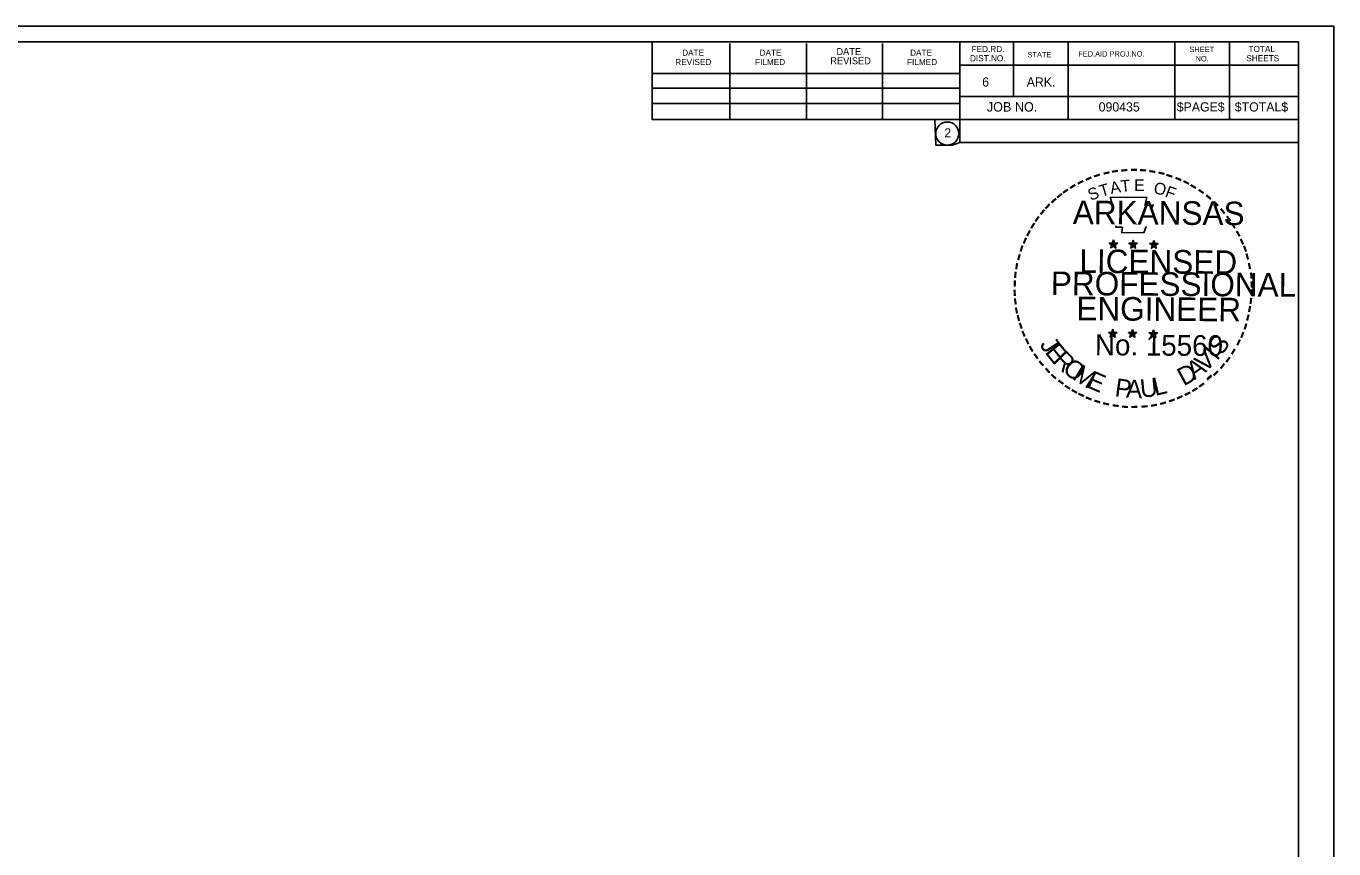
# Model space of a CAD drawing. Extents: x -1.3 to 32.1, y -0.2 to 20.7.
# Drawn here: x 15.42 to 32.07, y 10.27 to 20.75 of the extents above; entities that cross this region are included whole.
import ezdxf

# ---------------------------------------------------------------- set-up
doc = ezdxf.new("R2010")
doc.units = 0
for name, color, linetype in [('Level 1', 7, 'Continuous'), ('Level 49', 7, 'Continuous'), ('Level 62', 7, 'Continuous'), ('Level 63', 7, 'Continuous')]:
    doc.layers.add(name, color=color, linetype=linetype)

msp = doc.modelspace()

# ---------------------------------------------------------------- linework, layer by layer
at = {"layer": 'Level 1'}
for p, q in [((-0.001, 20.545), (31.617, 20.545)), ((23.391, 19.557), (23.391, 20.545)), ((24.377, 19.557), (24.377, 20.525)), ((25.353, 19.557), (25.353, 20.525)), ((26.321, 19.557), (26.321, 20.525)), ((27.307, 20.545), (27.307, 19.265)), ((27.991, 20.545), (27.991, 19.851)), ((28.685, 20.545), (28.685, 19.557)), ((30.043, 20.545), (30.043, 19.557)), ((30.737, 20.545), (30.737, 19.557)), ((31.617, -0.001), (31.617, 20.545)), ((23.391, 20.143), (27.307, 20.143)), ((31.617, 20.251), (27.307, 20.251)), ((31.617, 20.253), (31.617, 20.253)), ((23.391, 19.957), (27.307, 19.957)), ((31.617, 19.851), (27.307, 19.851)), ((23.391, 19.557), (23.391, 19.763)), ((23.391, 19.763), (27.307, 19.763)), ((31.617, 19.557), (23.391, 19.557)), ((27.307, 19.557), (27.307, 19.274)), ((27.307, 19.265), (31.617, 19.265))]:
    msp.add_line(p, q, dxfattribs=at)
msp.add_lwpolyline([(-0.001, 20.545), (23.391, 20.545), (23.391, 19.557), (27.307, 19.557), (27.307, 19.265), (31.617, 19.265), (31.617, 8.293), (-0.001, 8.293)], close=True, dxfattribs=at)
msp.add_circle((27.146, 19.379), 0.147, dxfattribs=at)
at = {"layer": 'Level 49'}
for p, q in [((29.208, 17.984), (29.262, 17.968)), ((29.208, 17.984), (29.247, 17.982)), ((29.208, 17.984), (29.247, 17.981)), ((29.208, 17.984), (29.243, 17.975)), ((29.208, 17.984), (29.243, 17.969)), ((29.208, 17.984), (29.243, 17.968)), ((29.208, 17.984), (29.243, 17.962)), ((29.262, 18.025), (29.255, 17.984)), ((29.262, 18.025), (29.255, 17.988)), ((29.262, 18.025), (29.258, 17.988)), ((29.262, 17.968), (29.262, 18.025)), ((29.262, 18.025), (29.271, 17.984)), ((29.262, 18.025), (29.269, 17.988)), ((29.262, 18.025), (29.264, 17.988)), ((29.314, 17.984), (29.262, 17.968)), ((29.314, 17.984), (29.266, 17.981)), ((29.314, 17.984), (29.271, 17.977)), ((29.314, 17.984), (29.271, 17.973)), ((29.314, 17.984), (29.279, 17.973)), ((29.314, 17.984), (29.284, 17.969)), ((29.314, 17.984), (29.286, 17.968)), ((29.458, 17.982), (29.512, 17.968)), ((29.458, 17.982), (29.497, 17.981)), ((29.458, 17.982), (29.497, 17.977)), ((29.458, 17.982), (29.497, 17.975)), ((29.458, 17.982), (29.495, 17.968)), ((29.458, 17.982), (29.495, 17.966)), ((29.458, 17.982), (29.495, 17.96)), ((29.512, 18.021), (29.505, 17.982)), ((29.512, 18.021), (29.505, 17.984)), ((29.512, 18.021), (29.506, 17.984)), ((29.512, 17.968), (29.512, 18.021)), ((29.512, 18.021), (29.521, 17.982)), ((29.512, 18.021), (29.519, 17.984)), ((29.512, 18.021), (29.514, 17.984)), ((29.564, 17.982), (29.512, 17.968)), ((29.564, 17.982), (29.518, 17.981)), ((29.564, 17.982), (29.521, 17.975)), ((29.564, 17.982), (29.521, 17.973)), ((29.564, 17.982), (29.529, 17.969)), ((29.564, 17.982), (29.534, 17.968)), ((29.564, 17.982), (29.536, 17.966)), ((29.723, 17.981), (29.777, 17.962)), ((29.723, 17.981), (29.766, 17.975)), ((29.723, 17.981), (29.762, 17.973)), ((29.723, 17.981), (29.762, 17.969)), ((29.723, 17.981), (29.76, 17.966)), ((29.723, 17.981), (29.76, 17.96)), ((29.723, 17.981), (29.76, 17.96)), ((29.777, 18.018), (29.768, 17.982)), ((29.777, 18.018), (29.773, 17.981)), ((29.777, 18.018), (29.773, 17.981)), ((29.777, 17.962), (29.777, 18.018)), ((29.777, 18.018), (29.788, 17.981)), ((29.777, 18.018), (29.784, 17.981)), ((29.777, 18.018), (29.781, 17.981)), ((29.829, 17.981), (29.777, 17.962)), ((29.829, 17.981), (29.782, 17.975)), ((29.829, 17.981), (29.788, 17.973)), ((29.829, 17.981), (29.788, 17.968)), ((29.829, 17.981), (29.795, 17.966)), ((29.829, 17.981), (29.797, 17.966)), ((29.829, 17.981), (29.803, 17.962)), ((29.23, 17.923), (29.262, 17.968)), ((29.23, 17.923), (29.243, 17.966)), ((29.23, 17.923), (29.247, 17.96)), ((29.23, 17.923), (29.249, 17.958)), ((29.23, 17.923), (29.255, 17.955)), ((29.23, 17.923), (29.262, 17.955)), ((29.23, 17.923), (29.262, 17.951)), ((29.293, 17.921), (29.262, 17.968)), ((29.293, 17.921), (29.262, 17.955)), ((29.293, 17.921), (29.262, 17.951)), ((29.293, 17.921), (29.266, 17.955)), ((29.293, 17.921), (29.271, 17.966)), ((29.293, 17.921), (29.271, 17.96)), ((29.293, 17.921), (29.277, 17.968)), ((29.481, 17.921), (29.512, 17.968)), ((29.481, 17.921), (29.497, 17.962)), ((29.481, 17.921), (29.497, 17.96)), ((29.481, 17.921), (29.499, 17.958)), ((29.481, 17.921), (29.505, 17.953)), ((29.481, 17.921), (29.512, 17.953)), ((29.481, 17.921), (29.512, 17.951)), ((29.544, 17.921), (29.512, 17.968)), ((29.544, 17.921), (29.512, 17.953)), ((29.544, 17.921), (29.512, 17.951)), ((29.544, 17.921), (29.518, 17.953)), ((29.544, 17.921), (29.521, 17.966)), ((29.544, 17.921), (29.521, 17.958)), ((29.544, 17.921), (29.527, 17.966)), ((29.744, 17.919), (29.777, 17.962)), ((29.744, 17.919), (29.762, 17.96)), ((29.744, 17.919), (29.766, 17.955)), ((29.744, 17.919), (29.766, 17.953)), ((29.744, 17.919), (29.777, 17.953)), ((29.744, 17.919), (29.773, 17.951)), ((29.744, 17.919), (29.781, 17.945)), ((29.807, 17.919), (29.777, 17.962)), ((29.807, 17.919), (29.777, 17.953)), ((29.807, 17.919), (29.777, 17.945)), ((29.807, 17.919), (29.782, 17.951)), ((29.807, 17.919), (29.788, 17.96)), ((29.807, 17.919), (29.788, 17.955)), ((29.807, 17.919), (29.792, 17.96)), ((29.201, 16.847), (29.255, 16.83)), ((29.201, 16.847), (29.24, 16.845)), ((29.201, 16.847), (29.238, 16.839)), ((29.201, 16.847), (29.238, 16.839)), ((29.201, 16.847), (29.238, 16.832)), ((29.201, 16.847), (29.238, 16.83)), ((29.201, 16.847), (29.238, 16.828)), ((29.219, 16.789), (29.255, 16.83)), ((29.219, 16.789), (29.238, 16.83)), ((29.219, 16.789), (29.24, 16.823)), ((29.219, 16.789), (29.242, 16.823)), ((29.219, 16.789), (29.255, 16.821)), ((29.219, 16.789), (29.247, 16.817)), ((29.219, 16.789), (29.255, 16.815)), ((29.255, 16.888), (29.243, 16.851)), ((29.255, 16.888), (29.247, 16.847)), ((29.255, 16.888), (29.249, 16.847)), ((29.284, 16.786), (29.251, 16.815)), ((29.255, 16.83), (29.255, 16.888)), ((29.255, 16.888), (29.262, 16.847)), ((29.255, 16.888), (29.262, 16.847)), ((29.255, 16.888), (29.255, 16.847)), ((29.306, 16.847), (29.255, 16.83)), ((29.284, 16.786), (29.255, 16.83)), ((29.284, 16.786), (29.255, 16.817)), ((29.284, 16.786), (29.256, 16.817)), ((29.306, 16.847), (29.258, 16.845)), ((29.306, 16.847), (29.262, 16.839)), ((29.306, 16.847), (29.262, 16.838)), ((29.284, 16.786), (29.262, 16.83)), ((29.284, 16.786), (29.262, 16.823)), ((29.306, 16.847), (29.269, 16.836)), ((29.284, 16.786), (29.269, 16.83)), ((29.306, 16.847), (29.273, 16.832)), ((29.306, 16.847), (29.277, 16.83)), ((29.451, 16.847), (29.505, 16.83)), ((29.451, 16.847), (29.49, 16.843)), ((29.451, 16.847), (29.49, 16.839)), ((29.451, 16.847), (29.49, 16.838)), ((29.451, 16.847), (29.488, 16.832)), ((29.451, 16.847), (29.488, 16.828)), ((29.451, 16.847), (29.488, 16.825)), ((29.469, 16.786), (29.505, 16.83)), ((29.469, 16.786), (29.49, 16.828)), ((29.469, 16.786), (29.49, 16.821)), ((29.469, 16.786), (29.492, 16.821)), ((29.469, 16.786), (29.497, 16.817)), ((29.469, 16.786), (29.505, 16.817)), ((29.469, 16.786), (29.505, 16.813)), ((29.505, 16.884), (29.495, 16.847)), ((29.505, 16.884), (29.497, 16.847)), ((29.505, 16.884), (29.499, 16.847)), ((29.534, 16.786), (29.503, 16.813)), ((29.505, 16.83), (29.505, 16.884)), ((29.505, 16.884), (29.512, 16.845)), ((29.505, 16.884), (29.512, 16.845)), ((29.505, 16.884), (29.505, 16.847)), ((29.555, 16.845), (29.505, 16.83)), ((29.534, 16.786), (29.505, 16.83)), ((29.534, 16.786), (29.505, 16.817)), ((29.534, 16.786), (29.506, 16.817)), ((29.555, 16.845), (29.51, 16.845)), ((29.555, 16.845), (29.512, 16.838)), ((29.555, 16.845), (29.512, 16.838)), ((29.534, 16.786), (29.512, 16.828)), ((29.534, 16.786), (29.512, 16.823)), ((29.555, 16.845), (29.519, 16.832)), ((29.534, 16.786), (29.519, 16.828)), ((29.555, 16.845), (29.525, 16.83)), ((29.555, 16.845), (29.527, 16.828)), ((29.716, 16.843), (29.77, 16.825)), ((29.716, 16.843), (29.755, 16.839)), ((29.716, 16.843), (29.755, 16.836)), ((29.716, 16.843), (29.753, 16.832)), ((29.716, 16.843), (29.753, 16.828)), ((29.716, 16.843), (29.751, 16.825)), ((29.716, 16.843), (29.751, 16.821)), ((29.736, 16.782), (29.77, 16.825)), ((29.736, 16.782), (29.753, 16.825)), ((29.736, 16.782), (29.755, 16.817)), ((29.736, 16.782), (29.758, 16.817)), ((29.736, 16.782), (29.762, 16.813)), ((29.736, 16.782), (29.768, 16.813)), ((29.77, 16.882), (29.76, 16.843)), ((29.77, 16.882), (29.762, 16.843)), ((29.77, 16.882), (29.766, 16.843)), ((29.799, 16.782), (29.768, 16.813)), ((29.77, 16.825), (29.77, 16.882)), ((29.77, 16.882), (29.777, 16.843)), ((29.77, 16.882), (29.777, 16.843)), ((29.77, 16.882), (29.77, 16.843)), ((29.821, 16.843), (29.77, 16.825)), ((29.799, 16.782), (29.77, 16.825)), ((29.799, 16.782), (29.773, 16.813)), ((29.821, 16.843), (29.775, 16.839)), ((29.821, 16.843), (29.777, 16.836)), ((29.821, 16.843), (29.777, 16.832)), ((29.799, 16.782), (29.777, 16.817)), ((29.799, 16.782), (29.781, 16.825)), ((29.799, 16.782), (29.782, 16.825)), ((29.821, 16.843), (29.788, 16.83)), ((29.821, 16.843), (29.79, 16.825)), ((29.821, 16.843), (29.792, 16.825)), ((29.736, 16.782), (29.77, 16.81)), ((29.799, 16.782), (29.768, 16.81))]:
    msp.add_line(p, q, dxfattribs=at)
for points in [[(29.219, 18.568), (29.256, 18.442)], [(29.745, 18.425), (29.768, 18.47), (29.662, 18.464), (29.686, 18.564), (29.219, 18.568)], [(29.292, 18.203), (29.292, 18.188), (29.375, 18.186), (29.368, 18.118), (29.647, 18.116), (29.677, 18.194)], [(29.262, 18.025), (29.293, 17.921), (29.208, 17.984), (29.314, 17.984), (29.23, 17.923), (29.262, 18.025)], [(29.512, 18.021), (29.544, 17.921), (29.458, 17.982), (29.564, 17.982), (29.481, 17.921), (29.512, 18.021)], [(29.777, 18.018), (29.807, 17.919), (29.723, 17.981), (29.829, 17.981), (29.744, 17.919), (29.777, 18.018)], [(29.255, 16.888), (29.284, 16.786), (29.201, 16.847), (29.306, 16.847), (29.219, 16.789), (29.255, 16.888)], [(29.505, 16.884), (29.534, 16.786), (29.451, 16.847), (29.555, 16.845), (29.469, 16.786), (29.505, 16.884)], [(29.77, 16.882), (29.799, 16.782), (29.716, 16.843), (29.821, 16.843), (29.736, 16.782), (29.77, 16.882)], [(30.464, 16.241), (30.457, 16.265), (30.501, 16.302)], [(30.498, 16.308), (30.505, 16.286), (30.46, 16.247)], [(30.505, 16.289), (30.46, 16.25)], [(30.505, 16.286), (30.462, 16.248)]]:
    msp.add_lwpolyline(points, dxfattribs=at)
for centre, radius in [((29.263, 17.967), 0.0259), ((29.263, 17.967), 0.0234), ((29.263, 17.967), 0.0217), ((29.263, 17.967), 0.0199), ((29.263, 17.967), 0.0174), ((29.263, 17.967), 0.0161), ((29.263, 17.967), 0.0149), ((29.263, 17.967), 0.0128), ((29.513, 17.965), 0.0259), ((29.513, 17.965), 0.0234), ((29.513, 17.965), 0.0217), ((29.513, 17.965), 0.0199), ((29.513, 17.965), 0.0174), ((29.513, 17.965), 0.0161), ((29.513, 17.965), 0.0149), ((29.779, 17.961), 0.0259), ((29.779, 17.961), 0.0234), ((29.779, 17.961), 0.0217), ((29.779, 17.961), 0.0199), ((29.263, 17.967), 0.0112), ((29.263, 17.967), 0.00933), ((29.263, 17.967), 0.00744), ((29.263, 17.967), 0.00555), ((29.263, 17.967), 0.00445), ((29.263, 17.967), 0.00216), ((29.513, 17.965), 0.0128), ((29.513, 17.965), 0.0112), ((29.513, 17.965), 0.00933), ((29.513, 17.965), 0.00744), ((29.513, 17.965), 0.00555), ((29.513, 17.965), 0.00445), ((29.513, 17.965), 0.00216), ((29.779, 17.961), 0.0174), ((29.779, 17.961), 0.0161), ((29.779, 17.961), 0.0149), ((29.779, 17.961), 0.0128), ((29.779, 17.961), 0.0112), ((29.779, 17.961), 0.00933), ((29.779, 17.961), 0.00744), ((29.779, 17.961), 0.00555), ((29.779, 17.961), 0.00445), ((29.779, 17.961), 0.00216), ((29.254, 16.83), 0.0259), ((29.254, 16.83), 0.0234), ((29.254, 16.83), 0.0217), ((29.254, 16.83), 0.0199), ((29.254, 16.83), 0.0174), ((29.254, 16.83), 0.0161), ((29.254, 16.83), 0.0149), ((29.254, 16.83), 0.0128), ((29.254, 16.83), 0.0112), ((29.254, 16.83), 0.00933), ((29.254, 16.83), 0.00744), ((29.254, 16.83), 0.00555), ((29.254, 16.83), 0.00445), ((29.254, 16.83), 0.00216), ((29.505, 16.828), 0.0259), ((29.505, 16.828), 0.0234), ((29.505, 16.828), 0.0217), ((29.505, 16.828), 0.0199), ((29.505, 16.828), 0.0174), ((29.505, 16.828), 0.0161), ((29.505, 16.828), 0.0149), ((29.505, 16.828), 0.0128), ((29.505, 16.828), 0.0112), ((29.505, 16.828), 0.00933), ((29.505, 16.828), 0.00744), ((29.505, 16.828), 0.00555), ((29.505, 16.828), 0.00445), ((29.505, 16.828), 0.00216), ((29.77, 16.825), 0.0259), ((29.77, 16.825), 0.0234), ((29.77, 16.825), 0.0217), ((29.77, 16.825), 0.0199), ((29.77, 16.825), 0.0174), ((29.77, 16.825), 0.0161), ((29.77, 16.825), 0.0149), ((29.77, 16.825), 0.0128), ((29.77, 16.825), 0.0112), ((29.77, 16.825), 0.00933), ((29.77, 16.825), 0.00744), ((29.77, 16.825), 0.00555), ((29.77, 16.825), 0.00445), ((29.77, 16.825), 0.00216)]:
    msp.add_circle(centre, radius, dxfattribs=at)
at = {"layer": 'Level 62'}
msp.add_lwpolyline([(-0.001, 20.545), (23.391, 20.545), (23.391, 20.545), (23.391, 19.557), (23.391, 19.557), (26.987, 19.557), (26.999, 19.232), (27.211, 19.232), (27.307, 19.265), (31.617, 19.265), (31.617, 8.293), (-0.001, 8.293)], close=True, dxfattribs=at)
at = {"layer": 'Level 63'}
msp.add_lwpolyline([(-1.263, -0.2), (32.067, -0.2), (32.067, 20.746), (-1.263, 20.746)], close=True, dxfattribs=at)

# ---------------------------------------------------------------- texts
at = {"layer": 'Level 1'}
for s, height, p in [('FED.RD.', 0.0782, (27.455, 20.417)), ('SHEET', 0.0684, (30.229, 20.417)), ('TOTAL', 0.0782, (30.981, 20.417)), ('REVISED', 0.0782, (23.683, 20.251)), ('DATE', 0.0782, (23.771, 20.369)), ('FILMED', 0.0782, (24.699, 20.251)), ('DATE', 0.0782, (24.757, 20.369)), ('REVISED', 0.0879, (25.657, 20.261)), ('DATE', 0.0879, (25.735, 20.379)), ('FILMED', 0.0782, (26.633, 20.251)), ('DATE', 0.0782, (26.673, 20.369)), ('DIST.NO.', 0.0782, (27.435, 20.299)), ('STATE', 0.0684, (28.167, 20.349)), ('FED.AID PROJ.NO.', 0.0684, (28.813, 20.359)), ('NO.', 0.0684, (30.307, 20.299)), ('SHEETS', 0.0782, (30.953, 20.299)), ('6', 0.117, (27.591, 19.977)), ('ARK.', 0.1172, (28.157, 19.977)), ('JOB NO.', 0.12, (27.65, 19.659)), ('090435', 0.1172, (29.073, 19.66)), ('$PAGE$', 0.1172, (30.067, 19.66)), ('$TOTAL$', 0.1172, (30.806, 19.66)), ('2', 0.117, (27.108, 19.329))]:
    msp.add_text(s, height=height, dxfattribs=at).set_placement(p)
at = {"layer": 'Level 49'}
for s, height, rotation, p in [('-', 0.24, 23.9096, (28.934, 18.699)), ('-', 0.24, 18.7785, (29.03, 18.74)), ('-', 0.24, 13.2326, (29.143, 18.775)), ('-', 0.24, 9.8217, (29.243, 18.799)), ('-', 0.24, 5.4992, (29.355, 18.814)), ('-', 0.24, 359.7886, (29.469, 18.825)), ('-', 0.24, 357.3454, (29.581, 18.822)), ('-', 0.24, 351.7641, (29.69, 18.812)), ('-', 0.24, 346.8073, (29.799, 18.796)), ('-', 0.24, 341.9386, (29.894, 18.77)), ('-', 0.24, 337.4575, (30.003, 18.736)), ('-', 0.24, 35.8341, (28.662, 18.54)), ('-', 0.24, 33.666, (28.749, 18.599)), ('-', 0.24, 28.3942, (28.84, 18.653)), ('S', 0.15, 21.1964, (28.969, 18.521)), ('T', 0.15, 16.006, (29.106, 18.571)), ('A', 0.15, 10.8156, (29.232, 18.609)), ('T', 0.15, 5.6252, (29.36, 18.633)), ('E', 0.15, 0.4347, (29.525, 18.647)), ('O', 0.15, 350.0539, (29.766, 18.616)), ('F', 0.15, 339.6731, (29.908, 18.579)), ('-', 0.24, 333.7235, (30.099, 18.697)), ('-', 0.24, 329.2433, (30.184, 18.653)), ('-', 0.24, 325.4651, (30.281, 18.596)), ('-', 0.24, 48.0254, (28.456, 18.351)), ('-', 0.24, 42.5646, (28.525, 18.421)), ('-', 0.24, 38.5531, (28.591, 18.483)), ('ARKANSAS', 0.3002, 359.6024, (28.743, 18.227)), ('-', 0.24, 320.1321, (30.372, 18.533)), ('-', 0.24, 315.181, (30.462, 18.458)), ('-', 0.24, 53.8349, (28.332, 18.194)), ('-', 0.24, 50.2166, (28.395, 18.279)), ('-', 0.24, 309.4821, (30.546, 18.375)), ('-', 0.24, 306.2546, (30.622, 18.284)), ('-', 0.24, 62.4738, (28.238, 18.021)), ('-', 0.24, 57.673, (28.284, 18.112)), ('-', 0.21, 303.2777, (30.696, 18.197)), ('-', 0.24, 299.2708, (30.742, 18.106)), ('-', 0.24, 67.3767, (28.199, 17.931)), ('-', 0.24, 294.2652, (30.79, 18.014)), ('-', 0.24, 75.0634, (28.134, 17.729)), ('-', 0.24, 71.9969, (28.163, 17.836)), ('LICENSED', 0.3002, 359.6024, (28.827, 17.605)), ('-', 0.24, 290.1752, (30.831, 17.931)), ('-', 0.24, 284.7257, (30.862, 17.842)), ('-', 0.24, 80.8037, (28.112, 17.623)), ('-', 0.24, 280.1517, (30.892, 17.729)), ('-', 0.24, 88.6646, (28.097, 17.414)), ('-', 0.24, 84.7887, (28.1, 17.519)), ('PROFESSIONAL', 0.30016, 359.6024, (28.464, 17.323)), ('-', 0.24, 276.1986, (30.918, 17.614)), ('-', 0.24, 273.9325, (30.925, 17.504)), ('-', 0.24, 93.7983, (28.1, 17.304)), ('-', 0.24, 269.5431, (30.929, 17.412)), ('-', 0.24, 98.5503, (28.112, 17.203)), ('-', 0.24, 101.3173, (28.128, 17.093)), ('ENGINEER', 0.3002, 359.6024, (28.788, 17.002)), ('-', 0.24, 260.5977, (30.912, 17.214)), ('-', 0.24, 263.1196, (30.925, 17.312)), ('-', 0.24, 105.0602, (28.154, 17.004)), ('-', 0.24, 255.365, (30.896, 17.112)), ('-', 0.24, 108.6898, (28.186, 16.912)), ('-', 0.24, 113.6667, (28.223, 16.819)), ('No. 15560', 0.2641, 359.6024, (29.025, 16.558)), ('-', 0.24, 247.4911, (30.837, 16.901)), ('-', 0.24, 252.4705, (30.87, 17.002)), ('-', 0.24, 115.3313, (28.269, 16.726)), ('-', 0.24, 120.0495, (28.321, 16.638)), ('J', 0.231, 303.9209, (28.315, 16.691)), ('E', 0.231, 308.618, (28.38, 16.594)), ('I', 0.231, 49.9999, (30.578, 16.478)), ('S', 0.231, 53.5227, (30.635, 16.544)), ('-', 0.24, 244.2221, (30.794, 16.808)), ('-', 0.24, 125.4958, (28.382, 16.554)), ('-', 0.24, 130.3205, (28.449, 16.471)), ('R', 0.231, 314.7784, (28.477, 16.476)), ('O', 0.231, 321.6761, (28.6, 16.357)), ('A', 0.231, 34.8903, (30.292, 16.237)), ('V', 0.231, 41.4844, (30.424, 16.332)), ('-', 0.24, 233.4476, (30.677, 16.599)), ('-', 0.24, 238.6736, (30.735, 16.697)), ('-', 0.24, 133.8262, (28.527, 16.389)), ('-', 0.24, 138.5362, (28.602, 16.319)), ('M', 0.231, 328.1357, (28.727, 16.259)), ('E', 0.231, 336.4966, (28.906, 16.156)), ('D', 0.231, 28.5809, (30.155, 16.16)), ('-', 0.24, 225.3677, (30.536, 16.43)), ('-', 0.24, 233.4476, (30.607, 16.517)), ('-', 0.24, 144.2487, (28.69, 16.258)), ('-', 0.24, 147.6922, (28.771, 16.2)), ('P', 0.231, 351.9783, (29.27, 16.037)), ('A', 0.231, 357.9896, (29.418, 16.017)), ('U', 0.231, 5.7635, (29.611, 16.016)), ('L', 0.231, 13.0992, (29.792, 16.038)), ('-', 0.24, 211.8515, (30.294, 16.226)), ('-', 0.24, 215.3387, (30.373, 16.284)), ('-', 0.24, 151.1728, (28.856, 16.152)), ('-', 0.24, 154.2026, (28.938, 16.113)), ('-', 0.24, 158.1636, (29.03, 16.073)), ('-', 0.24, 162.4007, (29.134, 16.041)), ('-', 0.24, 200.3208, (30.023, 16.087)), ('-', 0.24, 203.854, (30.116, 16.128)), ('-', 0.24, 206.9592, (30.21, 16.174)), ('-', 0.24, 167.1579, (29.24, 16.017)), ('-', 0.24, 172.7179, (29.355, 16)), ('-', 0.24, 176.1207, (29.468, 15.989)), ('-', 0.24, 181.1942, (29.579, 15.993)), ('-', 0.24, 185.4191, (29.701, 16.002)), ('-', 0.24, 190.8882, (29.812, 16.021)), ('-', 0.24, 195.0767, (29.921, 16.05))]:
    msp.add_text(s, height=height, rotation=rotation, dxfattribs=at).set_placement(p)

doc.saveas('drawing.dxf')
